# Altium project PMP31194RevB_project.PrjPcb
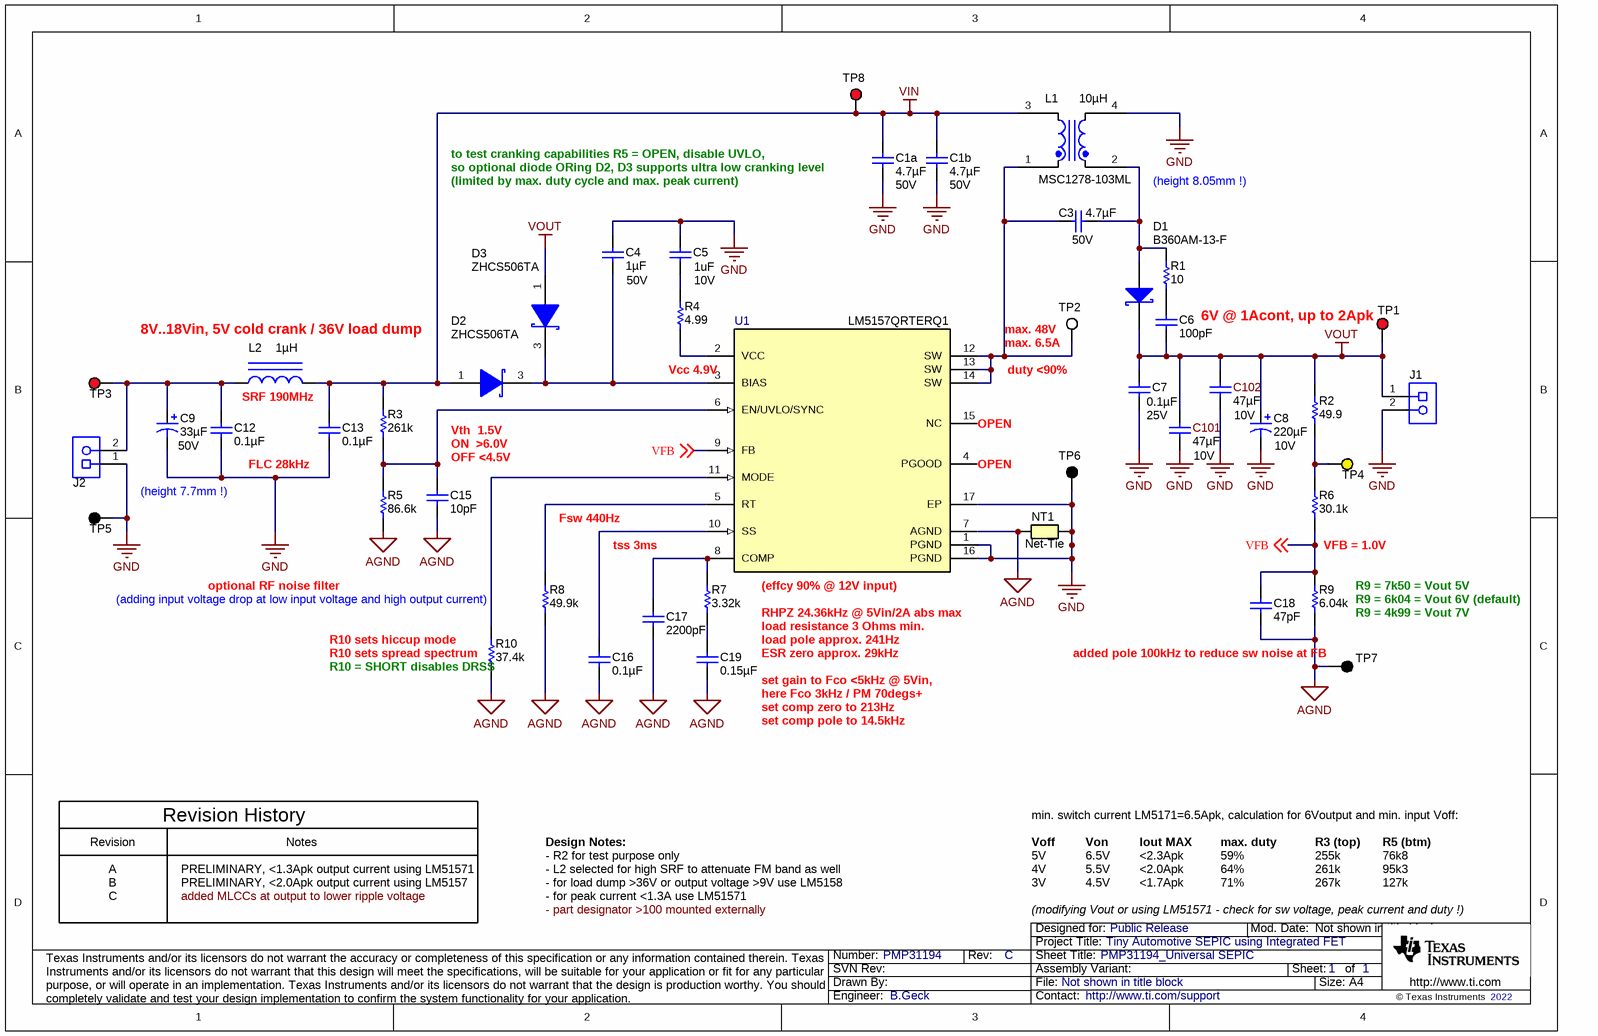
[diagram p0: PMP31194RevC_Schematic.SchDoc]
CopyrightYear: 2022; PCB_Layout: B.Geck; PCB_Rev: B; PRJ_Customer: Public Release; PRJ_Engineer: B.Geck; PRJ_Number: PMP31194; PRJ_Title: Tiny Automotive SEPIC using Integrated FET; SCH_Rev: C; TechSupport: http://www.ti.com/support; TID: N/A
1 sheet, 45 parts. Net scope: global (net labels, ports and power ports of the same name join across sheets).
Board file: PMP31194RevB_board.PcbDoc

## Sheet PMP31194RevC_Schematic.SchDoc: PMP31194_Universal SEPIC
size A4; Date: Not shown in title block; ApprovedBy: Not shown in title block; CheckedBy: Not shown in title block; Author: Not shown in title block; CompanyName: Not shown in title block; Engineer: Not shown in title block; Organization: Not shown in title block; Address1: Not shown in title block; Address2: Not shown in title block; Address3: Not shown in title block; Address4: Not shown in title block; DocumentNumber: 1; Revision: Use project parameter SCH_Rev; SheetNumber: 1; SheetTotal: 1; PageSetup: Record=PageOptions¦CenterHorizontal=True¦CenterVertical=True¦PrintScale=0.70¦XCorrection=1.00¦YCorrection=1.00¦PrintKind=0¦BorderSize=5000000¦LeftOffset=0¦BottomOffset=0¦Orientation=2¦PaperLength=1000¦PaperWidth=1000¦Scale=100¦PaperSource=15¦PrintQuality=600¦MediaType=1¦DitherType=10¦PaperKind=A4¦PrintScaleMode=1

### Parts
C1a  ValueDisplayed: 4.7µF  Value2: 50V  [1206_180]  (hidden comment: GRM31CR71H475KA12L)
C1b  ValueDisplayed: 4.7µF  Value2: 50V  [1206_180]  (hidden comment: GRM31CR71H475KA12L)
C3  ValueDisplayed: 4.7µF  Value2: 50V  [1206_180]  (hidden comment: GRM31CR71H475KA12L)
C4  Value2: 50V  Cap_F: 1µF  [0805_HV]  (hidden comment: GRM21BR71H105KA12L)
C5  VDC_V: 10V  ValueDisplayed: 1uF  [0805_HV]  (hidden comment: GRM21BR71A105KA01L)
C6  ValueDisplayed: 100pF  [0603]  (hidden comment: GCM1885C2A101JA16D)
C7  ValueDisplayed: 0.1µF  Value2: 25V  [0603]  (hidden comment: GRM188R71E104KA01D)
C8  ValueDisplayed: 220µF  Value2: 10V  [7343-31]  (hidden comment: T598D227M010ATE025)
C9  ValueDisplayed: 33µF  Value2: 50V  [SM_RADIAL_6.3BMM]  (hidden comment: EEHZC1H330XP)
C12  ValueDisplayed: 0.1µF  [0603]  (hidden comment: GCM188R71H104KA57D)
C13  ValueDisplayed: 0.1µF  [0603]  (hidden comment: GCM188R71H104KA57D)
C15  ValueDisplayed: 10pF  [0603]  (hidden comment: GRM1885C1H100JA01D)
C16  ValueDisplayed: 0.1µF  [0603]  (hidden comment: GRM188R71E104KA01D)
C17  ValueDisplayed: 2200pF  [0603]  (hidden comment: GRM188R71E222KA01D)
C18  ValueDisplayed: 47pF  [0603]  (hidden comment: GRM1885C1H470JA01D)
C19  ValueDisplayed: 0.15µF  [0603]  (hidden comment: GRM188R71C154KA01D)
C101  ValueDisplayed: 47µF  Value2: 10V  [1210_270]  (hidden comment: GRM32ER71A476KE15L)
C102  ValueDisplayed: 47µF  Value2: 10V  [1210_270]  (hidden comment: GRM32ER71A476KE15L)
D1  B360AM-13-F  [SMA]
D2  ZHCS506TA  [SOT-23]
D3  ZHCS506TA  [SOT-23]
J1  ED555/2DS  [TERM_BLK_ED555-2DS]  (value not drawn)
J2  ED555/2DS  [TERM_BLK_ED555-2DS]  (value not drawn)
L1  MSC1278-103ML  ValueDisplayed: 10µH  [MSD1278]
L2  ValueDisplayed: 1µH  [LPS3015]  (hidden comment: LPS3015-102MLB)
NT1  Net-Tie  [Net-Tie_10mil]  (net tie, no BOM)
R1  ValueDisplayed: 10  [0603]  (hidden comment: CRCW060310R0JNEAHP)
R2  ValueDisplayed: 49.9  [0603]  (hidden comment: CRCW060349R9FKEA)
R3  ValueDisplayed: 261k  [0603]  (hidden comment: CRCW0603261KFKEA)
R4  ValueDisplayed: 4.99  [0603]  (hidden comment: CRCW06034R99FKEA)
R5  ValueDisplayed: 86.6k  [0603]  (hidden comment: CRCW060386K6FKEA)
R6  ValueDisplayed: 30.1k  [0603]  (hidden comment: CRCW060330K1FKEA)
R7  ValueDisplayed: 3.32k  [0603]  (hidden comment: CRCW06033K32FKEA)
R8  ValueDisplayed: 49.9k  [0603]  (hidden comment: CRCW060349K9FKEA)
R9  ValueDisplayed: 6.04k  [0603]  (hidden comment: CRCW06036K04FKEA)
R10  ValueDisplayed: 37.4k  [0603]  (hidden comment: CRCW060337K4FKEA)
TP1  5010  [Keystone5010]  (value not drawn)
TP2  5012  [Keystone5012]  (value not drawn)
TP3  5010  [Keystone5010]  (value not drawn)
TP4  5014  [Keystone5014]  (value not drawn)
TP5  5011  [Keystone5011]  (value not drawn)
TP6  5011  [Keystone5011]  (value not drawn)
TP7  5011  [Keystone5011]  (value not drawn)
TP8  5010  [Keystone5010]  (value not drawn)
U1  LM5157QRTERQ1  [RTE0016K]

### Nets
AGND: C15.2 C16.2 C17.2 C18.2 C19.2 NT1.1 R5.1 R8.1 R9.1 R10.1 TP7.1 U1.7(AGND)
GND: C1a.2 C1b.2 C4.1 C5.2 C7.2 C8.2(-) C9.2(-) C12.2 C13.2 C101.2 C102.2 J1.2 J2.1 L1.4 NT1.2 TP5.1 TP6.1 U1.1(PGND) U1.16(PGND) U1.17(EP)
VIN: C1a.1 C1b.1 C13.1 D2.1(A) L1.3 L2.2 R3.2 TP8.1
VOUT: C6.2 C7.1 C8.1(+) C101.1 C102.1 D1.1(K) D3.1(A) J1.1 R2.2 TP1.1
VFB: C18.1 R6.1 R9.2 U1.9(FB) ; off-sheet VFB
NetC3_1: C3.1 D1.2(A) L1.2 R1.2
NetC3_2: C3.2 L1.1 TP2.1 U1.12(SW) U1.13(SW) U1.14(SW)
NetC4_2: C4.2 D2.3(K) D3.3(K) U1.3(BIAS)
NetC5_1: C5.1 R4.2
NetC6_1: C6.1 R1.1
NetC9_1: C9.1(+) C12.1 J2.2 L2.1 TP3.1
NetC15_1: C15.1 R3.1 R5.2 U1.6(EN/UVLO/SYNC)
NetC16_1: C16.1 U1.10(SS)
NetC17_1: C17.1 R7.2 U1.8(COMP)
NetC19_1: C19.1 R7.1
NetR2_1: R2.1 R6.2 TP4.1
NetR4_1: R4.1 U1.2(VCC)
NetR8_2: R8.2 U1.5(RT)
NetR10_2: R10.2 U1.11(MODE)

Not connected (* = marked no-connect by the designer): U1 4(PGOOD) 15(NC)

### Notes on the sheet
- so optional diode ORing D2, D3 supports ultra low cranking level
- (limited by max. duty cycle and max. peak current)
- to test cranking capabilities R5 = OPEN, disable UVLO,
- (height 8.05mm !)
- (near TP1) 6V @ 1Acont, up to 2Apk
- 8V..18Vin, 5V cold crank / 36V load dump
- (near U1) Vcc 4.9V
- (near TP2) max. 48V
- (near TP2) max. 6.5A
- (near TP2) duty <90%
- (near L2) SRF 190MHz
- Vth  1.5V
- ON  >6.0V
- (near U1) OPEN
- (height 7.7mm !)
- FLC 28kHz
- (near C15) OFF <4.5V
- Fsw 440Hz
- optional RF noise filter
- tss 3ms
- (near U1) (effcy 90% @ 12V input)
- VFB = 1.0V
- (near R9) R9 = 7k50 = Vout 5V
- (adding input voltage drop at low input voltage and high output current)
- (near R10) R10 sets hiccup mode
- (near R10) R10 sets spread spectrum
- RHPZ 24.36kHz @ 5Vin/2A abs max
- load resistance 3 Ohms min.
- load pole approx. 241Hz
- ESR zero approx. 29kHz
- (near TP7) added pole 100kHz to reduce sw noise at FB
- R9 = 6k04 = Vout 6V (default)
- R9 = 4k99 = Vout 7V
- (near R10) R10 = SHORT disables DRSS
- set gain to Fco <5kHz @ 5Vin,
- set comp zero to 213Hz
- set comp pole to 14.5kHz
- here Fco 3kHz / PM 70degs+
- Revision
- Revision History
- Notes
- Design Notes:
- - R2 for test purpose only
- min. switch current LM5171=6.5Apk, calculation for 6Voutput and min. input Voff:
- 5V
- Voff
- Von
- 6.5V
- <2.3Apk
- Iout MAX
- max. duty
- 59%
- 255k
- R3 (top)
- 76k8
- R5 (btm)
- A
- B
- C
- PRELIMINARY, <1.3Apk output current using LM51571
- PRELIMINARY, <2.0Apk output current using LM5157
- added MLCCs at output to lower ripple voltage
- - L2 selected for high SRF to attenuate FM band as well
- - for load dump >36V or output voltage >9V use LM5158
- - for peak current <1.3A use LM51571
- - part designator >100 mounted externally
- 4V
- 3V
- (modifying Vout or using LM51571 - check for sw voltage, peak current and duty !)
- 5.5V
- 4.5V
- <2.0Apk
- <1.7Apk
- 71%
- 64%
- 261k
- 267k
- 95k3
- 127k

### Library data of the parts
C1a C1b C3 = GRM31CR71H475KA12L: CAP, CERM, 4.7 µF, 50 V,+/- 10%, X7R, 1206; Manufacturer: MuRata; Polarized: N; CompType: Capacitor; Value: 4.7uF; U/M: EA; Cap_F: 0.0000047; Tolerance_%: 10; VDC_V: 50; TaMin_C: -55; TaMax_C: 125; Cap_Case: 1206; SizeArea_mm2: 5.12; SizeAreaWB_mm2: 10.92; SizeX_mm: 3.2; SizeY_mm: 1.6; SizeZ_mm: 1.8; AEC Category: Q200; Green_Lifecycle: Active; Green_REACh: Passed
C4 = CMP-0008350-2: CAP, CERM, 1 uF, 50 V, +/- 10%, X7R, 0805; Manufacturer: MuRata; TaMin_C: -55°C; Polarized: N; SizeAreaWB_mm2: 6.75; Value1: Unknown; U/M: EA; Value: 1uF; TaMax_C: 125°C; SizeZ_mm: 1.45; SizeX_mm: 2; SizeY_mm: 1.25; Cap_Case: 0805; SizeArea_mm2: 2.5; AEC Category: Q200
C5 = CMP-0008313-2: CAP, CERM, 1 uF, 10 V, +/- 10%, X7R, 0805; Manufacturer: MuRata; TaMin_C: -55°C; ESR_ohm: 7m; Polarized: N; SizeAreaWB_mm2: 6.75; Value1: 0.007 ohm; U/M: EA; Value: 1uF; TaMax_C: 125°C; SizeZ_mm: 1.45; SizeX_mm: 2; SizeY_mm: 1.25; Cap_Case: 0805; SizeArea_mm2: 2.5; Cap_F: 1µF; AEC Category: Q200
C6 = GCM1885C2A101JA16D: CAP, CERM, 100 pF, 100 V,+/- 5%, C0G/NP0, AEC-Q200 Grade 1, 0603; Manufacturer: MuRata; Polarized: N; CompType: Capacitor; Value: 100pF; U/M: EA; Cap_F: 0.0000000001; Tolerance_%: 5; VDC_V: 100; Value2: 100V; TaMin_C: -55; TaMax_C: 125; SizeArea_mm2: 1.28; SizeAreaWB_mm2: 4.68; SizeX_mm: 1.6; SizeY_mm: 0.8; SizeZ_mm: 1; AEC Category: Q200; AEC Qualified: Y
C7 = GRM188R71E104KA01D: CAP, CERM, 0.1 µF, 25 V,+/- 10%, X7R, 0603; Manufacturer: MuRata; Polarized: N; CompType: Capacitor; Value: 0.1uF; U/M: EA; Cap_F: 0.0000001; Tolerance_%: 10; VDC_V: 25; TaMin_C: -55; TaMax_C: 125; SizeArea_mm2: 1.28; SizeAreaWB_mm2: 4.68; SizeX_mm: 1.6; SizeY_mm: 0.8; SizeZ_mm: 1; AEC Category: Q200; Green_Lifecycle: Active; Green_REACh: Passed
C8 = T598D227M010ATE025: CAP, Tantalum Polymer, 220 µF, 10 V,+/- 20%, 0.025 ohm, AEC-Q200 Grade 1, 7343-31 SMD; Manufacturer: Kemet; Polarized: Y; CompType: Capacitor; Value: 220uF; U/M: EA; Cap_F: 0.00022; Tolerance_%: 20; VDC_V: 10; ESR_ohm: 0.025; IRMS_A: 3; TaMin_C: -55; TaMax_C: 125; Cap_Case: 7.3x4.3x3.1mm; SizeAreaWB_mm2: 58.59; SizeArea_mm2: 31.39; SizeX_mm: 7.3; SizeY_mm: 4.3; SizeZ_mm: 3.1; AEC Category: Q200; AEC Grade: 1
C9 = EEHZC1H330XP: CAP, Polymer Hybrid, 33 µF, 50 V,+/- 20%, 40 ohm, 6.3x7.7 SMD; Manufacturer: Panasonic; Polarized: Y; CompType: Capacitor; Value: 33uF; U/M: EA; Cap_F: 0.000033; Tolerance_%: 20; Value1: 40 ohm; VDC_V: 50; ESR_ohm: 40; IRMS_A: 1.1; TaMin_C: -55; TaMax_C: 125; SizeAreaWB_mm2: 79.98; SizeArea_mm2: 48.18; SizeX_mm: 7.3; SizeY_mm: 6.6; SizeZ_mm: 7.7; AEC Category: Q200; Green_Lifecycle: Active; Green_REACh: Passed
C12 C13 = GCM188R71H104KA57D: CAP, CERM, 0.1 µF, 50 V,+/- 10%, X7R, 0603; Manufacturer: MuRata; Polarized: N; CompType: Capacitor; Value: 0.1uF; U/M: EA; Cap_F: 0.0000001; Tolerance_%: 10; ESR_ohm: 0.02; Value1: 0.02 ohm; VDC_V: 50; Value2: 50V; IRMS_A: 1.84; TaMin_C: -55; TaMax_C: 125; SizeArea_mm2: 1.28; SizeAreaWB_mm2: 4.68; SizeX_mm: 1.6; SizeY_mm: 0.8; SizeZ_mm: 1; AEC Category: Q200; Green_Lifecycle: Active; Green_REACh: Passed
C15 = GRM1885C1H100JA01D: CAP, CERM, 10 pF, 50 V,+/- 5%, C0G/NP0, 0603; Manufacturer: MuRata; Polarized: N; CompType: Capacitor; Value: 10pF; U/M: EA; Cap_F: 0.00000000001; Tolerance_%: 5; VDC_V: 50; Value2: 50V; TaMin_C: -55; TaMax_C: 125; SizeArea_mm2: 1.28; SizeAreaWB_mm2: 4.68; SizeX_mm: 1.6; SizeY_mm: 0.8; SizeZ_mm: 1; AEC Category: Q200; Green_Lifecycle: Active; Green_REACh: Passed
C16 = GRM188R71E104KA01D: CAP, CERM, 0.1 µF, 25 V,+/- 10%, X7R, 0603; Manufacturer: MuRata; Polarized: N; CompType: Capacitor; Value: 0.1uF; U/M: EA; Cap_F: 0.0000001; Tolerance_%: 10; VDC_V: 25; Value2: 25V; TaMin_C: -55; TaMax_C: 125; SizeArea_mm2: 1.28; SizeAreaWB_mm2: 4.68; SizeX_mm: 1.6; SizeY_mm: 0.8; SizeZ_mm: 1; AEC Category: Q200; Green_Lifecycle: Active; Green_REACh: Passed
C17 = GRM188R71E222KA01D: CAP, CERM, 2200 pF, 25 V,+/- 10%, X7R, 0603; Manufacturer: MuRata; Polarized: N; CompType: Capacitor; Value: 2200pF; U/M: EA; Cap_F: 0.0000000022; Tolerance_%: 10; VDC_V: 25; Value2: 25V; TaMin_C: -55; TaMax_C: 125; SizeArea_mm2: 1.28; SizeAreaWB_mm2: 4.68; SizeX_mm: 1.6; SizeY_mm: 0.8; SizeZ_mm: 1; AEC Category: Q200; Green_Lifecycle: Active; Green_REACh: Passed
C18 = GRM1885C1H470JA01D: CAP, CERM, 47 pF, 50 V,+/- 5%, C0G/NP0, 0603; Manufacturer: MuRata; Polarized: N; CompType: Capacitor; Value: 47pF; U/M: EA; Cap_F: 0.000000000047; Tolerance_%: 5; VDC_V: 50; Value2: 50V; TaMin_C: -55; TaMax_C: 125; SizeArea_mm2: 1.28; SizeAreaWB_mm2: 4.68; SizeX_mm: 1.6; SizeY_mm: 0.8; SizeZ_mm: 1; AEC Category: Q200; Green_Lifecycle: Active; Green_REACh: Passed
C19 = GRM188R71C154KA01D: CAP, CERM, 0.15 µF, 16 V,+/- 10%, X7R, 0603; Manufacturer: MuRata; Polarized: N; CompType: Capacitor; Value: 0.15uF; U/M: EA; Cap_F: 0.00000015; Tolerance_%: 10; VDC_V: 16; Value2: 16V; TaMin_C: -55; TaMax_C: 125; SizeArea_mm2: 1.28; SizeAreaWB_mm2: 4.68; SizeX_mm: 1.6; SizeY_mm: 0.8; SizeZ_mm: 1; AEC Category: Q200; Green_Lifecycle: Active; Green_REACh: Passed
C101 C102 = GRM32ER71A476KE15L: CAP, CERM, 47 µF, 10 V,+/- 10%, X7R, 1210; Manufacturer: MuRata; Polarized: N; CompType: Capacitor; Value: 47uF; U/M: EA; Cap_F: 0.000047; Tolerance_%: 10; TaMin_C: -55; TaMax_C: 125; Cap_Case: 1210; SizeArea_mm2: 8; SizeAreaWB_mm2: 14.7; SizeX_mm: 3.2; SizeY_mm: 2.5; SizeZ_mm: 2.7; AEC Category: Q200; Green_Lifecycle: Active; Green_REACh: Passed
D1 = B360AM-13-F: Diode, Schottky, 60 V, 3 A, AEC-Q101, SMA; Manufacturer: Diodes Inc.; U/M: EA; Vf_V: 0.7; Value: 60V; Value1: 3A; Value2: 0.7V; Io_A: 3; Vr_V: 60; TJmax_C: 150; SizeAreaWB_mm2: 37.3428; SizeArea_mm2: 16.3228; SizeX_mm: 5.59; SizeY_mm: 2.92; SizeZ_mm: 2.87; AEC Category: Q101; AEC Qualified: Y; Green_Lifecycle: Not Set; Green_REACh: Incomplete
D2 D3 = ZHCS506TA: Diode, Schottky, 60 V, 0.5 A, SOT-23; Manufacturer: Diodes Inc.; U/M: EA; Vf_V: 0.63; Value: 60V; Value1: 0.5A; Value2: 0.63V; Io_A: 0.5; Vr_V: 60; TJmax_C: 125; SizeAreaWB_mm2: 14; SizeArea_mm2: 7.5; SizeX_mm: 2.5; SizeY_mm: 3; SizeZ_mm: 1.1; AEC Category: Q101; Green_Lifecycle: Active; Green_REACh: Passed
J1 J2 = CMP-0074913-1: Terminal Block, 3.5mm Pitch, 2x1, TH; Manufacturer: On-Shore Technology; Cert_VDE: Y; CNHeader: False; Current_A: 6A; Green_Lifecycle: Active; Shrouded: N; Gender: Female; Green_REACh: Passed; Voltage_V: 150V; Row_Count: 1; Pitch_mm: 3.5; ContactFinish: Brass; CT: True
L1 = MSD1278-103ML: Coupled inductor, 10 µH, 10.5 A, 0.058 ohm, AEC-Q200 Grade 3, TH; Manufacturer: Coilcraft; SymbolCreator: a0412235; SizeAreaWB_mm2: 204.49; SizeArea_mm2: 151.29; SizeX_mm: 12.3; SizeZ_mm: 8.05; Value: 10uH; Ind_H: 10.0E-6; DCR_ohm: 0.058; AEC Category: Q200; AEC Qualified: Y; AEC Grade: 3
L2 = LPS3015-102MLB: Inductor, Shielded Drum Core, Ferrite, 1 µH, 2 A, 0.08 ohm, SMD; Manufacturer: Coilcraft; Value: 1uH; Ind_H: 1.0E-6; Imax_A: 2; Irms: 2A @ 40C rise; Isat: 2.1A @ 30% inductance drop; DCR_ohm: 0.08; Value2: 2A; SizeAreaWB_mm2: 15.6025; SizeArea_mm2: 8.7025; SizeX_mm: 2.95; SizeZ_mm: 1.4; AEC Category: Q200; Green_Lifecycle: Not Set; Green_REACh: Incomplete
NT1 = Net-Tie: Single point connection between nets.; SymbolCreator: codlsc
R1 = CRCW060310R0JNEAHP: RES, 10, 5%, 0.25 W, 0603; Manufacturer: Vishay-Dale; CompType: Resistor; Value: 10; Value_Code: 10R0; Tolerance_%: 5; Power_W: 0.25; Value2: 0.25W; VDC_V: 75; TempCo: 200 ppm/C; SizeArea_mm2: 1.28; SizeX_mm: 1.6; SizeY_mm: 0.8; SizeZ_mm: 1; EIA_Code: E24; U/M: EA; AEC Category: Q200; Green_Lifecycle: Active; Green_REACh: Passed
R2 = CMP-0022448-4: RES, 49.9, 1%, 0.1 W, AEC-Q200 Grade 0, 0603; Manufacturer: Vishay-Dale; Power_W: 100mW; TempCo: 100 ppm/C; Value_Code: 49R9; Value: 49.9; EIA_Code: E96; SizeX_mm: 1.6; SizeY_mm: 0.8; SizeZ_mm: 1; Value2: 0.1W; SizeArea_mm2: 1.28; AEC Qualified: Y; VDC_V: 75V; AEC Category: Q200; AEC Grade: 0
R3 = CRCW0603261KFKEA: RES, 261 k, 1%, 0.1 W, 0603; Manufacturer: Vishay-Dale; CompType: Resistor; Value: 261k; Res_ohm: 261000; Tolerance_%: 1; Power_W: 0.1; Value2: 0.1W; VDC_V: 75; TempCo: 100 ppm/C; SizeArea_mm2: 1.28; SizeX_mm: 1.6; SizeY_mm: 0.8; EIA_Code: E96; U/M: EA; AEC Category: Q200; Green_Lifecycle: Active; Green_REACh: Passed
R4 = CRCW06034R99FKEA: RES, 4.99, 1%, 0.1 W, 0603; Manufacturer: Vishay-Dale; CompType: Resistor; Value: 4.99; Value_Code: 4R99; Tolerance_%: 1; Power_W: 0.1; Value2: 0.1W; VDC_V: 75; TempCo: 100 ppm/C; SizeArea_mm2: 1.28; SizeX_mm: 1.6; SizeY_mm: 0.8; EIA_Code: E96; U/M: EA; AEC Category: Q200; Green_Lifecycle: Active; Green_REACh: Passed
R5 = CRCW060386K6FKEA: RES, 86.6 k, 1%, 0.1 W, 0603; Manufacturer: Vishay-Dale; CompType: Resistor; Value: 86.6k; Res_ohm: 86600; Value_Code: 86k6; Tolerance_%: 1; Power_W: 0.1; Value2: 0.1W; VDC_V: 75; TempCo: 100 ppm/C; SizeArea_mm2: 1.28; SizeX_mm: 1.6; SizeY_mm: 0.8; EIA_Code: E96; U/M: EA; AEC Category: Q200; Green_Lifecycle: Active; Green_REACh: Passed
R6 = CRCW060330K1FKEA: RES, 30.1 k, 1%, 0.1 W, 0603; Manufacturer: Vishay-Dale; CompType: Resistor; Value: 30.1k; Res_ohm: 30100; Value_Code: 30k1; Tolerance_%: 1; Power_W: 0.1; Value2: 0.1W; VDC_V: 75; TempCo: 100 ppm/C; SizeArea_mm2: 1.28; SizeX_mm: 1.6; SizeY_mm: 0.8; EIA_Code: E96; U/M: EA; AEC Category: Q200; Green_Lifecycle: Active; Green_REACh: Passed
R7 = CRCW06033K32FKEA: RES, 3.32 k, 1%, 0.1 W, 0603; Manufacturer: Vishay-Dale; CompType: Resistor; Value: 3.32k; Res_ohm: 3320; Value_Code: 3k32; Tolerance_%: 1; Power_W: 0.1; Value2: 0.1W; VDC_V: 75; TempCo: 100 ppm/C; SizeArea_mm2: 1.28; SizeX_mm: 1.6; SizeY_mm: 0.8; EIA_Code: E96; U/M: EA; AEC Category: Q200; Green_Lifecycle: Active; Green_REACh: Passed
R8 = CRCW060349K9FKEA: RES, 49.9 k, 1%, 0.1 W, 0603; Manufacturer: Vishay-Dale; CompType: Resistor; Value: 49.9k; Res_ohm: 49900; Value_Code: 49k9; Tolerance_%: 1; Power_W: 0.1; Value2: 0.1W; VDC_V: 75; TempCo: 100 ppm/C; SizeArea_mm2: 1.28; SizeX_mm: 1.6; SizeY_mm: 0.8; EIA_Code: E96; U/M: EA; AEC Category: Q200; Green_Lifecycle: Active; Green_REACh: Passed
R9 = CRCW06036K04FKEA: RES, 6.04 k, 1%, 0.1 W, 0603; Manufacturer: Vishay-Dale; CompType: Resistor; Value: 6.04k; Res_ohm: 6040; Value_Code: 6k04; Tolerance_%: 1; Power_W: 0.1; Value2: 0.1W; VDC_V: 75; TempCo: 100 ppm/C; SizeArea_mm2: 1.28; SizeX_mm: 1.6; SizeY_mm: 0.8; EIA_Code: E96; U/M: EA; AEC Category: Q200; Green_Lifecycle: Active; Green_REACh: Passed
R10 = CMP-0022360-4: RES, 37.4 k, 1%, 0.1 W, AEC-Q200 Grade 0, 0603; Manufacturer: Vishay-Dale; Power_W: 100mW; TempCo: 100 ppm/C; Value_Code: 37k4; Value: 37.4k; EIA_Code: E96; SizeX_mm: 1.6; SizeY_mm: 0.8; SizeZ_mm: 1; Value2: 0.1W; SizeArea_mm2: 1.28; AEC Qualified: Y; VDC_V: 75V; AEC Category: Q200; AEC Grade: 0
TP1 TP3 TP8 = CMP-0055147-1: Test Point, Multipurpose, Red, TH; Manufacturer: Keystone; CNHeader: FALSE; Green_Lifecycle: Active; Green_REACh: Passed; ContactFinish: Silver; CT: TRUE
TP2 = 5012: Test Point, Multipurpose, White, TH; Manufacturer: Keystone; CompType: Test Point Loop; ContactFinish: Silver; Green_Lifecycle: Active; Green_REACh: Passed
TP4 = CMP-0055151-1: Test Point, Multipurpose, Yellow, TH; Manufacturer: Keystone; CNHeader: FALSE; Green_Lifecycle: Active; Green_REACh: Passed; ContactFinish: Silver; CT: TRUE
TP5-TP7 = CMP-0055148-1: Test Point, Multipurpose, Black, TH; Manufacturer: Keystone; CNHeader: FALSE; Green_Lifecycle: Active; Green_REACh: Passed; ContactFinish: Silver; CT: TRUE
U1 = CMP-0861102-1: 2.2MHz Wide VIN Boost/Sepic/Flyback Converter with Dual Random Spread Spectrum, RTE0016K (WQFN-16); Alternate Manufacturer: Texas Instruments; SizeX_mm: 3; SizeZ_mm: 0.8; SizeArea_mm2: 9; SizeAreaWB_mm2: 16; AEC Category: Q200; CompType: IC; AEC Qualified: N

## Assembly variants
publ: not fitted D3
